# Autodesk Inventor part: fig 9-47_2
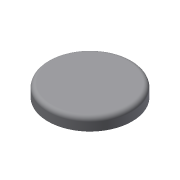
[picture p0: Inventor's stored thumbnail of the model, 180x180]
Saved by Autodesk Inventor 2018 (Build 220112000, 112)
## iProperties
Created: 2013-03
Part Number: fig 9-47_2
Material: Generic
Document SubType Name: Modeling
Designer: CADCIM
Density: 1 g/cm^3
Appearance: Default
Author: CADCIM
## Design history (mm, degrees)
sketch "Sketch1"
  geometry: C1 r 2.5 at (0, 0); 1 further point
  constraints: 1 centre point, 1 coincident
  dimensions: "d0" = 5 diameter of C1
extrude "Extrusion1" new body sketch "Sketch1" distance "d2" = 0.75; taper "d3" = 0 deg
fillet "Fillet1" dims "d4" = 0.25
body "Solid1"
